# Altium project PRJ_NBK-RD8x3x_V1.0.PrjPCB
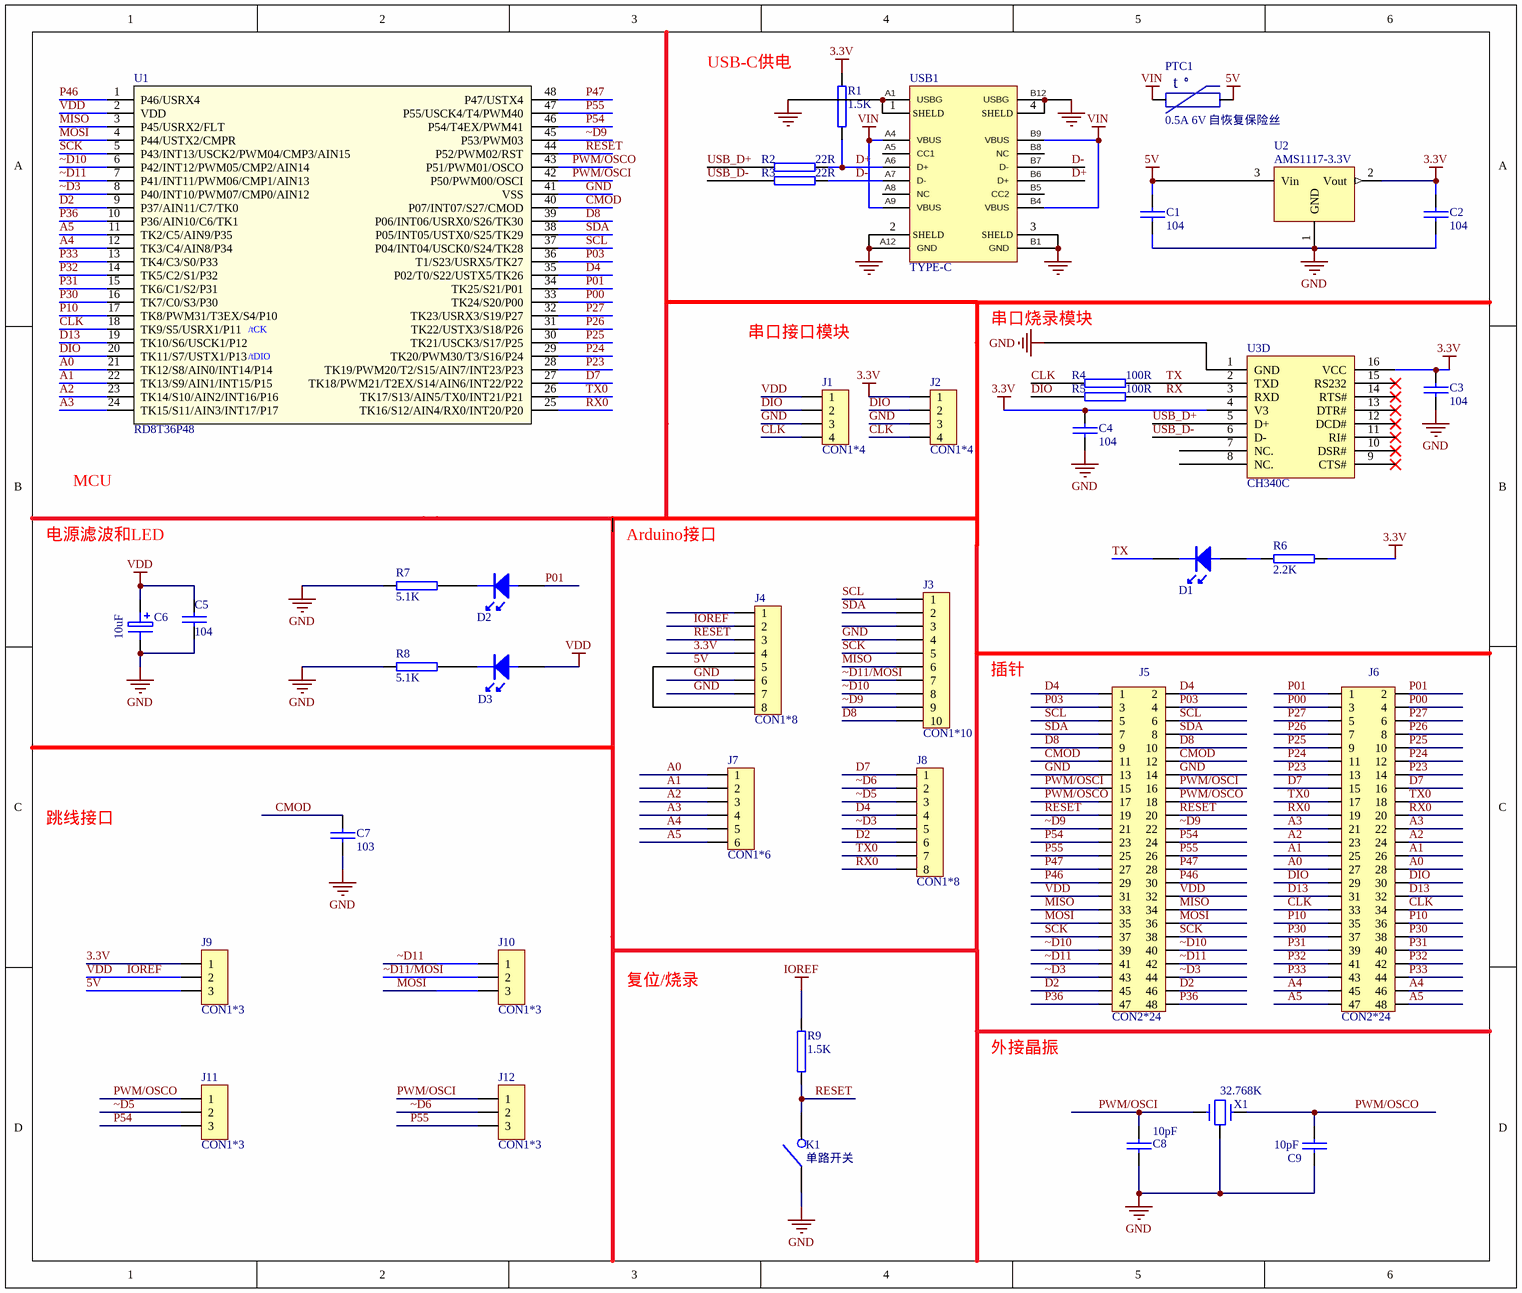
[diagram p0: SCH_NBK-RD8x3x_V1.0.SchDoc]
1 sheet, 40 parts. Net scope: global (net labels, ports and power ports of the same name join across sheets).
Board file: PCB_NBK-RD8x3x_V1.0.PcbDoc

## Sheet SCH_NBK-RD8x3x_V1.0.SchDoc
size 284 x 241 mm

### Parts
C1  104  [C0805]
C2  104  [C0805]
C3  104  [C0805]
C4  104  [C0805]
C5  104  [C0805]
C6  10uF  [A-3216]
C7  103  [C0805]
C8  10pF  [C0603]
C9  10pF  [C0603]
D1  LED-GREED  [LED0805]  (value not drawn)
D2  LED-GREED  [LED0805]  (value not drawn)
D3  LED-GREED  [LED0805]  (value not drawn)
J1  CON1*4  [CON1*4(P=2.54)]
J2  CON1*4  [CON1*4(P=2.54)]
J3  CON1*10  [CON1*10(P=2.54)]
J4  CON1*8  [CON1*8(P=2.54)]
J5  CON2*24  [CON2*24(P=2.54)]
J6  CON2*24  [CON2*24(P=2.54)]
J7  CON1*6  [CON1*6(P=2.54)]
J8  CON1*8  [CON1*8(P=2.54)]
J9  CON1*3  [CON1*3(P=2.54)]
J10  CON1*3  [CON1*3(P=2.54)]
J11  CON1*3  [CON1*3(P=2.54)]
J12  CON1*3  [CON1*3(P=2.54)]
K1  单路开关  [SW-SMD_UK-B0246-SP25Y]
PTC1  0.5A 6V 自恢复保险丝  [R1206]
R1  1.5K  [R0805]
R2  22R  [R0805]
R3  22R  [R0805]
R4  100R  [R0805]
R5  100R  [R0805]
R6  2.2K  [R0805]
R7  5.1K  [R0805]
R8  5.1K  [R0805]
R9  1.5K  [R0805]
U1  RD8T36P48  [LQFP-48(7X7)]
U2  AMS1117-3.3V  [SOT-223]
U3  CH340C  [SOP16]  (part D of 4)
USB1  TYPE-C  [TYPE-C1]
X1  32.768K  [32768]

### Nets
3.3V: C2.1 C3.1 C4.1 J2.1 J4.4 J9.1 R1.1 R6.1 U2.2(Vout) U3.4(V3) U3.16(VCC)
5V: C1.1 J4.5 J4.8 J9.3 PTC1.2 U2.3(Vin)
GND: C1.2 C2.2 C3.2 C4.2 C5.2 C6.2 C7.2 C8.2 C9.2 J1.3 J2.3 J3.4 J4.6 J4.7 J5.13 J5.14 K1.1 R7.2 R8.2 U1.41(VSS) U2.1(GND) U3.1(GND) USB1.1(SHELD) USB1.2(SHELD) USB1.3(SHELD) USB1.4(SHELD) USB1.A1(USBG) USB1.A12(GND) USB1.B1(GND) USB1.B12(USBG) X1.0
IOREF: C5.1 C6.1 D3.1 J1.1 J4.2 J5.31 J5.32 J9.2 R9.2 U1.2(VDD)  [also labelled VDD]
VIN: PTC1.1 USB1.A4(VBUS) USB1.A9(VBUS) USB1.B4(VBUS) USB1.B9(VBUS)
A0: J6.27 J6.28 J7.1 U1.21(TK12/S8/AIN0/INT14/P14)
A1: J6.25 J6.26 J7.2 U1.22(TK13/S9/AIN1/INT15/P15)
A2: J6.23 J6.24 J7.3 U1.23(TK14/S10/AIN2/INT16/P16)
A3: J6.21 J6.22 J7.4 U1.24(TK15/S11/AIN3/INT17/P17)
A4: J6.45 J6.46 J7.5 U1.12(TK3/C4/AIN8/P34)
A5: J6.47 J6.48 J7.6 U1.11(TK2/C5/AIN9/P35)
CLK: J1.4 J2.4 J6.33 J6.34 R4.2 U1.18(TK9/S5/USRX1/P11)
CMOD: C7.1 J5.11 J5.12 U1.40(P07/INT07/S27/CMOD)
D2: J5.45 J5.46 J8.6 U1.9(P37/AIN11/C7/TK0)
D4: J5.1 J5.2 J8.4 U1.35(P02/T0/S22/USTX5/TK26)
D7: J6.15 J6.16 J8.1 U1.27(TK18/PWM21/T2EX/S14/AIN6/INT22/P22)
D8: J3.10 J5.9 J5.10 U1.39(P06/INT06/USRX0/S26/TK30)
D13: J6.31 J6.32 U1.19(TK10/S6/USCK1/P12)
D+: R1.2 R2.1 USB1.A6(D+) USB1.B6(D+)
D-: R3.1 USB1.A7(D-) USB1.B7(D-)
DIO: J1.2 J2.2 J6.29 J6.30 R5.2 U1.20(TK11/S7/USTX1/P13)
MISO: J3.6 J5.33 J5.34 U1.3(P45/USRX2/FLT)
MOSI: J5.35 J5.36 J10.3 U1.4(P44/USTX2/CMPR)
P00: J6.3 J6.4 U1.33(TK24/S20/P00)
P01: D2.1 J6.1 J6.2 U1.34(TK25/S21/P01)
P03: J5.3 J5.4 U1.36(T1/S23/USRX5/TK27)
P10: J6.35 J6.36 U1.17(TK8/PWM31/T3EX/S4/P10)
P23: J6.13 J6.14 U1.28(TK19/PWM20/T2/S15/AIN7/INT23/P23)
P24: J6.11 J6.12 U1.29(TK20/PWM30/T3/S16/P24)
P25: J6.9 J6.10 U1.30(TK21/USCK3/S17/P25)
P26: J6.7 J6.8 U1.31(TK22/USTX3/S18/P26)
P27: J6.5 J6.6 U1.32(TK23/USRX3/S19/P27)
P30: J6.37 J6.38 U1.16(TK7/C0/S3/P30)
P31: J6.39 J6.40 U1.15(TK6/C1/S2/P31)
P32: J6.41 J6.42 U1.14(TK5/C2/S1/P32)
P33: J6.43 J6.44 U1.13(TK4/C3/S0/P33)
P36: J5.47 J5.48 U1.10(P36/AIN10/C6/TK1)
P46: J5.29 J5.30 U1.1(P46/USRX4)
P47: J5.27 J5.28 U1.48(P47/USTX4)
P54: J5.23 J5.24 J11.3 U1.46(P54/T4EX/PWM41)
P55: J5.25 J5.26 J12.3 U1.47(P55/USCK4/T4/PWM40)
PWM/OSCI: C8.1 J5.15 J5.16 J12.1 U1.42(P50/PWM00/OSCI) X1.1
PWM/OSCO: C9.1 J5.17 J5.18 J11.1 U1.43(P51/PWM01/OSCO) X1.2
RESET: J4.3 J5.19 J5.20 K1.2 R9.1 U1.44(P52/PWM02/RST)
RX: R5.1 U3.3(RXD)
RX0: J6.19 J6.20 J8.8 U1.25(TK16/S12/AIN4/RX0/INT20/P20)
SCK: J3.5 J5.37 J5.38 U1.5(P43/INT13/USCK2/PWM04/CMP3/AIN15)
SCL: J3.1 J5.5 J5.6 U1.37(P04/INT04/USCK0/S24/TK28)
SDA: J3.2 J5.7 J5.8 U1.38(P05/INT05/USTX0/S25/TK29)
TX: D1.2 R4.1 U3.2(TXD)
TX0: J6.17 J6.18 J8.7 U1.26(TK17/S13/AIN5/TX0/INT21/P21)
USB_D+: R2.2 U3.5(D+)
USB_D-: R3.2 U3.6(D-)
~D3: J5.43 J5.44 J8.5 U1.8(P40/INT10/PWM07/CMP0/AIN12)
~D5: J8.3 J11.2
~D6: J8.2 J12.2
~D9: J3.9 J5.21 J5.22 U1.45(P53/PWM03)
~D10: J3.8 J5.39 J5.40 U1.6(P42/INT12/PWM05/CMP2/AIN14)
~D11: J5.41 J5.42 J10.1 U1.7(P41/INT11/PWM06/CMP1/AIN13)
~D11/MOSI: J3.7 J10.2
NetD1_1: D1.1 R6.2
NetD2_2: D2.2 R7.1
NetD3_2: D3.2 R8.1

Not connected (* = marked no-connect by the designer): J3 3; J4 1; U3 7(NC.) 8(NC.) 9(CTS#)* 10(DSR#)* 11(RI#)* 12(DCD#)* 13(DTR#)* 14(RTS#)* 15(RS232)*; USB1 A5(CC1) A8(NC) B5(CC2) B8(NC)

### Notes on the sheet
- USB-C供电
- 串口接口模块
- 串口烧录模块
- MCU
- 电源滤波和LED
- Arduino接口
- 插针
- 跳线接口
- 复位/烧录
- 外接晶振

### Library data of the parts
C1-C5 C7-C9 = CAP1: 贴片电容
C6 = T-A/4.7uF/16V
D1 D2 = LED-CP: 蓝色
D3 = LED-CP: 红色
K1 = KEY-6
PTC1 = PTC-MZ11-06A200-400RM: 6V 500mA PTC自恢复保险丝
R1-R9 = R0805: 功率: 1/8W
U1 = RD8T37P48: 电压:2.0V-5.5V;ROM:128KB;RAM:内部256B+外部8KB+ PWM&LCD 80B;32/16/8/4MHz
U2 = LDO-SPX1117M3: LDO；1A；SOT-223-3
USB1 = TYPE-C1: Type-c母座16pin 快充闪充usb3.0沉板母座连接器
X1 = CRYSTAL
